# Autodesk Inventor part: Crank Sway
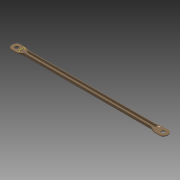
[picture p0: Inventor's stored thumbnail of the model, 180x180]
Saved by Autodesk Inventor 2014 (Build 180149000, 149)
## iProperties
Created: 2006-03
Part Number: Crank Sway
Document SubType Name: Modeling
Designer: Autodesk, Inc.
Material: Stainless Steel, 440C
Mass: 132.412 g
Surface Area: 221.126 cm^2
Volume: 17.0854 cm^3
Density: 7.75 g/cm^3
Appearance: Brindle
Author: Autodesk, Inc.
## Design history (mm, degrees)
sketch "Sketch1"
  geometry: L1 (0, 0)-(0, 1.6); L2 (0, 1.6)-(4.6, 1.6); L3 (4.6, 1.6)-(4.6, 8); L4 (4.6, 8)-(6.2, 8); L5 (6.2, 8)-(6.2, 1.5); L6 (4.7, 0)-(0, 0); L7 (0, 9.662)-(0, -1.973) reference; L8 (-4.6, 1.6)-(-4.6, 8); L9 (-4.6, 8)-(-6.2, 8); L10 (-6.2, 8)-(-6.2, 1.5); L11 (0, 1.6)-(-4.6, 1.6); L12 (-4.7, 0)-(0, 0); A1 r 1.5 centre (4.7, 1.5) between (4.7, 0) and (6.2, 1.5); A2 r 1.5 centre (-4.7, 1.5) between (-6.2, 1.5) and (-4.7, 0)
  constraints: 22 end point, 6 symmetric about line, 4 parallel, 4 point on circle, 2 centre point, 2 perpendicular, 2 tangent, 1 vertical, 1 other
  dimensions: "d1" = 4.6 distance between parallel lines of L3 L1; "d2" = 8 distance between parallel lines of L6 L4; "d3" = 1.6 distance between parallel lines of L5 L3; "d4" = 1.5 radius of A1
extrude "Extrusion1" new body sketch "Sketch1" distance "d5" = 175; taper "d6" = 0 deg
workplane "Work Plane1"
sketch "Sketch2"
  geometry: L1 (-1.6, 0)-(9.6, 0) reference; L2 (3, 12)-(5, 12); L3 (5, 12)-(5, -12); L4 (5, -12)-(3, -12); L5 (3, -12)-(3, 12); L6 (3, 12)-(5, -12); L7 (1.5, 6.2)-(8, 6.2) reference; L8 (8, -6.2)-(1.5, -6.2) reference; L9 (0, -4.7)-(0, 4.7) reference; 2 further points
  constraints: 10 end point, 2 midpoint, 2 parallel, 1 horizontal, 1 perpendicular
  dimensions: "d8" = 4 distance from line of point (4, 0) L9; "d9" = 2 distance of L2.start L2.end; "d10" = 24 distance of L2.end L3.end
loft "Loft1" sketch "Sketch2" dims "d11" = 0, "d12" = 90 deg, "d13" = 0, "d14" = 90 deg
  node "Edges1"
sketch "Sketch3"
  geometry: L1 (2, 12.374)-(2, 18.469) reference; L2 (2, 19.993)-(0, 19.993) reference; L3 (2, 18.469)-(2, 19.993) reference; L4 (2, 3.612)-(2, 12.374) reference; L5 (2, -2.483)-(2, 3.612) reference; L6 (2, -4.007)-(2, -2.483) reference; L7 (0, -4.007)-(2, -4.007) reference; L8 (0, 0)-(0, -4.007) reference; L9 (0, 15.986)-(0, 0) reference; L10 (0, 19.993)-(0, 15.986) reference; 1 further point
extrude "Extrusion2" join sketch "Sketch3" distance "d15" = 20; taper "d16" = 0 deg
sketch "Sketch4"
  geometry: L1 (-49.747, 12)-(250.958, 12) reference; L2 (0, 24)-(0, 0); A1 r 14 centre (7.211, 12) between (0, 24) and (0, 0); 1 further point
  constraints: 3 point on circle, 2 end point, 1 centre point, 1 perpendicular, 1 point on line
  dimensions: "d17" = 14 radius of A1
extrude "Extrusion3" join sketch "Sketch4" stored distance "d18" = 20; taper "d19" = 0 deg
sketch "Sketch5"
  geometry: L1 (-69.747, 4.381)-(230.958, 4.381) reference; L2 (0, 12.374)-(0, -3.612) reference; C1 r 5 at (-14, 4.381); 1 further point
  constraints: 1 centre point, 1 point on line
  dimensions: "d20" = 10 diameter of C1; "d21" = 14 distance from line of C1.centre L2
extrude "Extrusion4" cut sketch "Sketch5" stored distance "d22" = 20; taper "d23" = 0 deg
mirror "Mirror1"
body "Solid1"
other parameters: "d7" = 13
